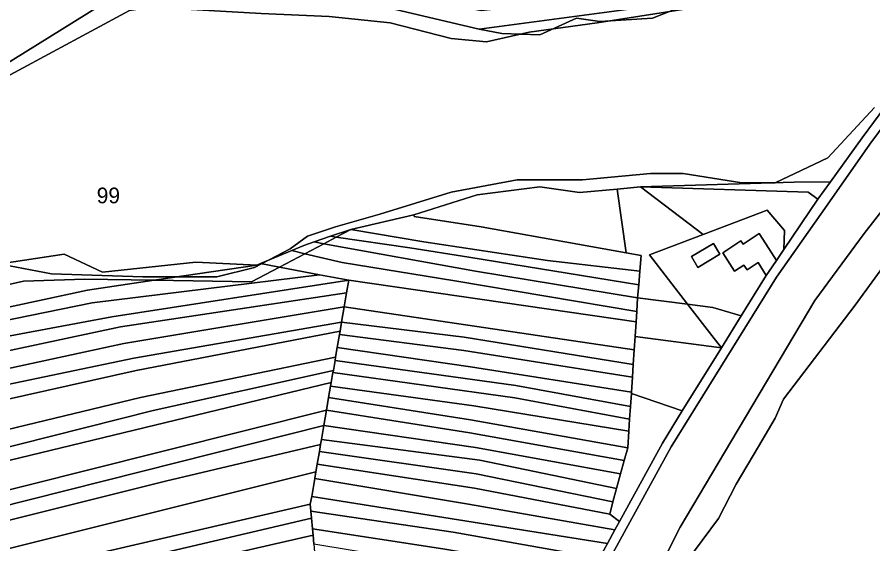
# Model space of a CAD drawing. Extents: x -537068 to -534056, y -1176840 to -1172401.
# Drawn here: x -535241.9 to -534968.9, y -1175937.1 to -1175769.2 of the extents above; entities that cross this region are included whole.
import ezdxf

# ---------------------------------------------------------------- set-up
doc = ezdxf.new("R2010")
doc.units = 0
for name, color, linetype in [('95560013', 7, 'Continuous'), ('95600013', 7, 'Continuous'), ('95630013', 7, 'Continuous'), ('95640013', 7, 'Continuous'), ('95660013', 7, 'Continuous')]:
    doc.layers.add(name, color=color, linetype=linetype)

msp = doc.modelspace()

# ---------------------------------------------------------------- linework, layer by layer
at = {"layer": '95560013'}
for points in [[(-535093.8, -1175835.96), (-535115.19, -1175832.75), (-535115.29, -1175832.21), (-535095.1, -1175825.79), (-535075.08, -1175823.28), (-535062.41, -1175825.11), (-535050.4, -1175823.98), (-535047.57, -1175844.26)], [(-535023.04, -1175838.49), (-535040.14, -1175844.98), (-535028.03, -1175860.61), (-535043.9, -1175858.67), (-535043.57, -1175854.49), (-535043.22, -1175850.16), (-535042.81, -1175845.11), (-535047.57, -1175844.26), (-535050.4, -1175823.98), (-535043.04, -1175823.29)], [(-535002.6, -1175830.73), (-535023.04, -1175838.49), (-535043.04, -1175823.29), (-534989.46, -1175824.91), (-534986.43, -1175827.21), (-534997.31, -1175843.24), (-534997.06, -1175837.16)], [(-535002.6, -1175830.73), (-534997.06, -1175837.16), (-534997.31, -1175843.24), (-534999.65, -1175846.69), (-535002.01, -1175842.95), (-535005.09, -1175838.09), (-535010.29, -1175841.55), (-535011.03, -1175840.44), (-535016.76, -1175844.25), (-535012.96, -1175850.13), (-535010, -1175848.19), (-535009.01, -1175849.71), (-535005.48, -1175847.43), (-535002.86, -1175851.51), (-535006.68, -1175857.67), (-535010.83, -1175864.37), (-535019.94, -1175861.74), (-535028.03, -1175860.61), (-535040.14, -1175844.98), (-535023.04, -1175838.49)], [(-535093.8, -1175835.96), (-535047.57, -1175844.26), (-535042.81, -1175845.11), (-535043.22, -1175850.16), (-535072.62, -1175846.76), (-535112.1, -1175840.82), (-535135.41, -1175836.85), (-535115.29, -1175832.21), (-535115.19, -1175832.75)], [(-535043.57, -1175854.49), (-535097.72, -1175845.7), (-535116.6, -1175842.75), (-535140.05, -1175839.3), (-535135.41, -1175836.85), (-535112.1, -1175840.82), (-535072.62, -1175846.76), (-535043.22, -1175850.16)], [(-535140.05, -1175839.3), (-535116.6, -1175842.75), (-535097.72, -1175845.7), (-535043.57, -1175854.49), (-535043.9, -1175858.67), (-535095.66, -1175850.09), (-535144.02, -1175841.39)], [(-535102.18, -1175853.19), (-535138.14, -1175847.43), (-535150.05, -1175844.57), (-535144.02, -1175841.39), (-535095.66, -1175850.09), (-535043.9, -1175858.67), (-535044.19, -1175863.05)], [(-535026.7, -1175845.5), (-535024.68, -1175848.95), (-535017.7, -1175844.74), (-535019.74, -1175841.36)], [(-535044.4, -1175866.25), (-535136.05, -1175853.05), (-535145.38, -1175851.28), (-535158.18, -1175848.85), (-535150.05, -1175844.57), (-535138.14, -1175847.43), (-535102.18, -1175853.19), (-535044.19, -1175863.05)], [(-535301.85, -1175877.35), (-535297.59, -1175872.96), (-535219.37, -1175856.17), (-535198.16, -1175853.04), (-535167.13, -1175853.57), (-535158.18, -1175848.85), (-535145.38, -1175851.28), (-535217.93, -1175860.21)], [(-535136.05, -1175853.05), (-535136.74, -1175857.04), (-535208.89, -1175867.91), (-535313.65, -1175890.19), (-535307.82, -1175883.5), (-535306.83, -1175882.48), (-535211.67, -1175864.71)], [(-535301.85, -1175877.35), (-535217.93, -1175860.21), (-535145.38, -1175851.28), (-535136.05, -1175853.05), (-535211.67, -1175864.71), (-535306.83, -1175882.48)], [(-535219.37, -1175856.17), (-535297.59, -1175872.96), (-535295.86, -1175871.17), (-535274.11, -1175861.12), (-535239.83, -1175853.35), (-535220.25, -1175852.67), (-535198.16, -1175853.04)], [(-535044.99, -1175875.22), (-535137.5, -1175861.46), (-535136.74, -1175857.04), (-535136.05, -1175853.05), (-535044.4, -1175866.25), (-535044.71, -1175871.01)], [(-535136.74, -1175857.04), (-535137.5, -1175861.46), (-535207.84, -1175873.23), (-535319.39, -1175897.37), (-535317.62, -1175894.74), (-535313.65, -1175890.19), (-535208.89, -1175867.91)], [(-535020.24, -1175870.67), (-535017.19, -1175874.61), (-535044.71, -1175871.01), (-535044.4, -1175866.25), (-535044.19, -1175863.05), (-535043.9, -1175858.67), (-535028.03, -1175860.61)], [(-535137.5, -1175861.46), (-535138.35, -1175866.38), (-535204.63, -1175877.91), (-535254.59, -1175888.3), (-535324.19, -1175904.5), (-535319.39, -1175897.37), (-535207.84, -1175873.23)], [(-535044.99, -1175875.22), (-535045.3, -1175879.92), (-535099.27, -1175871.18), (-535138.35, -1175866.38), (-535137.5, -1175861.46)], [(-535020.24, -1175870.67), (-535028.03, -1175860.61), (-535019.94, -1175861.74), (-535010.83, -1175864.37), (-535017.19, -1175874.61)], [(-535324.19, -1175904.5), (-535254.59, -1175888.3), (-535204.63, -1175877.91), (-535138.35, -1175866.38), (-535138.84, -1175869.24), (-535203.94, -1175881.8), (-535253.84, -1175892.92), (-535330.15, -1175913.36)], [(-535138.84, -1175869.24), (-535138.35, -1175866.38), (-535099.27, -1175871.18), (-535045.3, -1175879.92), (-535045.56, -1175883.91), (-535099.38, -1175875.46), (-535139.02, -1175870.29)], [(-535245.21, -1175900.68), (-535297.9, -1175915.28), (-535335.82, -1175927.11), (-535336.74, -1175923.15), (-535330.15, -1175913.36), (-535253.84, -1175892.92), (-535203.94, -1175881.8), (-535138.84, -1175869.24), (-535139.02, -1175870.29), (-535139.74, -1175874.45), (-535140.26, -1175877.53), (-535202.54, -1175890.38)], [(-535099.38, -1175875.46), (-535045.56, -1175883.91), (-535045.88, -1175888.7), (-535097.19, -1175880.69), (-535139.74, -1175874.45), (-535139.02, -1175870.29)], [(-535045.91, -1175889.14), (-535045.88, -1175888.7), (-535045.56, -1175883.91), (-535045.3, -1175879.92), (-535044.99, -1175875.22), (-535044.71, -1175871.01), (-535017.19, -1175874.61), (-535029.65, -1175894.7)], [(-535140.45, -1175878.61), (-535140.26, -1175877.53), (-535139.74, -1175874.45), (-535097.19, -1175880.69), (-535045.88, -1175888.7), (-535045.91, -1175889.14), (-535046.18, -1175893.26), (-535082.73, -1175886.57)], [(-535297.9, -1175915.28), (-535245.21, -1175900.68), (-535202.54, -1175890.38), (-535140.26, -1175877.53), (-535140.45, -1175878.61), (-535140.99, -1175881.77), (-535198.45, -1175894.61), (-535295.84, -1175919.08), (-535335.09, -1175930.24), (-535335.82, -1175927.11)], [(-535140.45, -1175878.61), (-535082.73, -1175886.57), (-535046.18, -1175893.26), (-535046.45, -1175897.3), (-535083.13, -1175890.54), (-535141.12, -1175882.5), (-535140.99, -1175881.77)], [(-535141.12, -1175882.5), (-535141.67, -1175885.68), (-535297.4, -1175923.22), (-535334.35, -1175933.46), (-535335.09, -1175930.24), (-535295.84, -1175919.08), (-535198.45, -1175894.61), (-535140.99, -1175881.77)], [(-535046.45, -1175897.3), (-535046.7, -1175901.19), (-535096.14, -1175893.12), (-535141.86, -1175886.78), (-535141.67, -1175885.68), (-535141.12, -1175882.5), (-535083.13, -1175890.54)], [(-535334.35, -1175933.46), (-535297.4, -1175923.22), (-535141.67, -1175885.68), (-535141.86, -1175886.78), (-535142.48, -1175890.39), (-535143.19, -1175894.5), (-535220.72, -1175913.88), (-535332.39, -1175941.92)], [(-535096.14, -1175893.12), (-535046.7, -1175901.19), (-535047.05, -1175906.47), (-535097.2, -1175897.49), (-535142.48, -1175890.39), (-535141.86, -1175886.78)], [(-535048.17, -1175910.48), (-535097.45, -1175901.68), (-535143.19, -1175894.5), (-535142.48, -1175890.39), (-535097.2, -1175897.49), (-535047.05, -1175906.47)], [(-535047.05, -1175906.47), (-535046.7, -1175901.19), (-535046.45, -1175897.3), (-535046.18, -1175893.26), (-535045.91, -1175889.14), (-535029.65, -1175894.7), (-535036.02, -1175904.98), (-535049.68, -1175929.91), (-535052.8, -1175927.58), (-535051.86, -1175923.72), (-535050.67, -1175919.47), (-535049.37, -1175914.79), (-535048.17, -1175910.48)], [(-535144.02, -1175899.33), (-535331.33, -1175946.51), (-535332.39, -1175941.92), (-535220.72, -1175913.88), (-535143.19, -1175894.5)], [(-535095.62, -1175906.33), (-535144.02, -1175899.33), (-535143.19, -1175894.5), (-535097.45, -1175901.68), (-535048.17, -1175910.48), (-535049.37, -1175914.79)], [(-535145.06, -1175905.39), (-535194.58, -1175917.13), (-535330.29, -1175951), (-535331.33, -1175946.51), (-535144.02, -1175899.33), (-535144.8, -1175903.85)], [(-535144.02, -1175899.33), (-535095.62, -1175906.33), (-535049.37, -1175914.79), (-535050.67, -1175919.47), (-535094.22, -1175910.43), (-535144.8, -1175903.85)], [(-535144.8, -1175903.85), (-535094.22, -1175910.43), (-535050.67, -1175919.47), (-535051.86, -1175923.72), (-535095.41, -1175914.8), (-535145.44, -1175907.61), (-535145.06, -1175905.39)], [(-535194.58, -1175917.13), (-535145.06, -1175905.39), (-535145.44, -1175907.61), (-535146.13, -1175911.66), (-535146.55, -1175914.1), (-535328.33, -1175959.48), (-535330.29, -1175951)], [(-535051.86, -1175923.72), (-535052.8, -1175927.58), (-535095.95, -1175919.32), (-535146.13, -1175911.66), (-535145.44, -1175907.61), (-535095.41, -1175914.8)], [(-535052.8, -1175927.58), (-535049.68, -1175929.91), (-535051.15, -1175932.6), (-535097.85, -1175924.46), (-535146.92, -1175916.27), (-535146.55, -1175914.1), (-535146.13, -1175911.66), (-535095.95, -1175919.32)], [(-535148.33, -1175924.47), (-535326.87, -1175965.76), (-535328.33, -1175959.48), (-535146.55, -1175914.1), (-535146.92, -1175916.27), (-535147.9, -1175921.98)], [(-535051.15, -1175932.6), (-535053.54, -1175936.95), (-535101.05, -1175929.43), (-535147.9, -1175921.98), (-535146.92, -1175916.27), (-535097.85, -1175924.46)], [(-535055.84, -1175941.16), (-535062, -1175940.6), (-535102.78, -1175933.38), (-535148.13, -1175926.69), (-535148.33, -1175924.47), (-535147.9, -1175921.98), (-535101.05, -1175929.43), (-535053.54, -1175936.95)], [(-535148.13, -1175926.69), (-535147.93, -1175928.92), (-535290.32, -1175962.24), (-535326.01, -1175969.46), (-535326.87, -1175965.76), (-535148.33, -1175924.47)], [(-535102.78, -1175933.38), (-535062, -1175940.6), (-535062.78, -1175945.98), (-535106.07, -1175938.71), (-535147.63, -1175932.3), (-535147.93, -1175928.92), (-535148.13, -1175926.69)], [(-535147.93, -1175928.92), (-535147.63, -1175932.3), (-535147.45, -1175934.33), (-535288.27, -1175966.48), (-535325.11, -1175973.34), (-535326.01, -1175969.46), (-535290.32, -1175962.24)], [(-535063.51, -1175950.98), (-535147.2, -1175937.21), (-535147.45, -1175934.33), (-535147.63, -1175932.3), (-535106.07, -1175938.71), (-535062.78, -1175945.98)], [(-535146.32, -1175947.1), (-535282.18, -1175976.18), (-535321.72, -1175983.04), (-535323.82, -1175978.94), (-535325.11, -1175973.34), (-535288.27, -1175966.48), (-535147.45, -1175934.33), (-535147.2, -1175937.21), (-535146.77, -1175942.01)]]:
    msp.add_lwpolyline(points, close=True, dxfattribs=at)
at = {"layer": '95600013'}
msp.add_lwpolyline([(-535336.79, -1175832.88), (-535317.96, -1175809.63), (-535313.29, -1175805.13), (-535301.28, -1175793.55), (-535286.39, -1175776.99), (-535271.4, -1175765.94), (-535247.87, -1175747.4), (-535227.44, -1175729.49), (-535216.91, -1175723.46), (-535201.51, -1175713.09), (-535168.68, -1175739.06), (-535159.9, -1175742.34), (-535152.61, -1175745.06), (-535149.83, -1175762.25), (-535207.84, -1175760.65), (-535247.13, -1175785.26), (-535307.86, -1175812.82), (-535328.63, -1175827.45), (-535350.95, -1175850.74)], close=True, dxfattribs=at)
at = {"layer": '95630013'}
for points in [[(-535247.13, -1175785.26), (-535207.84, -1175760.65), (-535191.06, -1175762.77), (-535169.69, -1175762.63), (-535149.83, -1175762.25), (-535125.27, -1175766.1), (-535121.13, -1175766.75), (-535094.47, -1175772.94), (-535087.2, -1175774.4), (-535075.1, -1175774.78), (-535063.37, -1175769.44), (-535055.93, -1175770.6), (-535039.2, -1175769.49), (-535024.33, -1175763.57), (-535019.28, -1175766.12), (-535002.34, -1175764.96), (-534963.81, -1175759.59)], [(-535048.44, -1175967.44), (-535030.38, -1175931.76), (-535016.19, -1175907.93), (-534987.38, -1175859.54), (-534971.62, -1175838.1), (-534919.46, -1175771.3)], [(-534919.46, -1175771.3), (-534971.62, -1175838.1), (-534987.38, -1175859.54), (-535016.19, -1175907.93), (-535030.38, -1175931.76), (-535048.44, -1175967.44)], [(-534950.61, -1175778.33), (-534972.28, -1175807.68), (-534982.43, -1175821.7), (-534993.98, -1175821.82), (-535043.04, -1175823.29), (-535050.4, -1175823.98), (-535062.41, -1175825.11), (-535075.08, -1175823.28), (-535095.1, -1175825.79), (-535115.29, -1175832.21), (-535135.41, -1175836.85), (-535141.85, -1175839.03), (-535147.14, -1175840.83), (-535150.37, -1175841.93), (-535154.26, -1175843.56), (-535164.2, -1175847.71), (-535165.43, -1175848.22), (-535184.89, -1175847.28), (-535214.67, -1175850.44), (-535226.82, -1175844.7), (-535248.82, -1175848.04)], [(-535063.2, -1175960.77), (-535033.24, -1175906.1), (-534999.62, -1175852.1), (-534983.44, -1175829.08), (-534969.88, -1175809.65), (-534947.07, -1175779.02)]]:
    msp.add_lwpolyline(points, dxfattribs=at)
for points in [[(-535055.93, -1175770.6), (-535063.37, -1175769.44), (-535075.1, -1175774.78), (-535087.2, -1175774.4), (-535094.47, -1175772.94), (-535024.33, -1175763.57), (-535039.2, -1175769.49)], [(-534993.98, -1175821.82), (-534982.43, -1175821.7), (-534986.43, -1175827.21), (-534989.46, -1175824.91), (-535043.04, -1175823.29)], [(-535141.85, -1175839.03), (-535135.41, -1175836.85), (-535140.05, -1175839.3)], [(-535140.05, -1175839.3), (-535144.02, -1175841.39), (-535147.14, -1175840.83), (-535141.85, -1175839.03)], [(-535144.02, -1175841.39), (-535150.05, -1175844.57), (-535154.26, -1175843.56), (-535150.37, -1175841.93), (-535147.14, -1175840.83)], [(-535266.46, -1175853.08), (-535248.82, -1175848.04), (-535226.82, -1175844.7), (-535214.67, -1175850.44), (-535184.89, -1175847.28), (-535165.43, -1175848.22), (-535198.16, -1175853.04), (-535220.25, -1175852.67), (-535239.83, -1175853.35), (-535274.11, -1175861.12), (-535295.86, -1175871.17), (-535280.94, -1175860.21)], [(-535150.05, -1175844.57), (-535158.18, -1175848.85), (-535164.2, -1175847.71), (-535154.26, -1175843.56)], [(-535164.2, -1175847.71), (-535158.18, -1175848.85), (-535167.13, -1175853.57), (-535198.16, -1175853.04), (-535165.43, -1175848.22)]]:
    msp.add_lwpolyline(points, close=True, dxfattribs=at)
at = {"layer": '95640013'}
for points in [[(-535025.18, -1175758.03), (-535004.49, -1175753.79), (-534961.92, -1175746.47), (-534964.16, -1175752.21), (-535024.33, -1175763.57), (-535094.47, -1175772.94), (-535121.13, -1175766.75), (-535141.07, -1175741.96), (-535121.28, -1175756.78), (-535112.39, -1175763.44), (-535093.81, -1175767.01), (-535079.13, -1175765.46), (-535050.13, -1175761.47)], [(-535010, -1175848.19), (-535012.96, -1175850.13), (-535016.76, -1175844.25), (-535011.03, -1175840.44), (-535010.29, -1175841.55), (-535005.09, -1175838.09), (-535002.01, -1175842.95), (-534999.65, -1175846.69), (-535002.19, -1175850.43), (-535002.86, -1175851.51), (-535005.48, -1175847.43), (-535009.01, -1175849.71)], [(-535019.74, -1175841.36), (-535017.7, -1175844.74), (-535024.68, -1175848.95), (-535026.7, -1175845.5)]]:
    msp.add_lwpolyline(points, close=True, dxfattribs=at)
for points in [[(-534947.07, -1175779.02), (-534969.88, -1175809.65), (-534983.44, -1175829.08), (-534999.62, -1175852.1), (-535033.24, -1175906.1), (-535063.2, -1175960.77)], [(-535055.84, -1175941.16), (-535053.54, -1175936.95), (-535051.15, -1175932.6), (-535049.68, -1175929.91), (-535036.02, -1175904.98), (-535029.65, -1175894.7), (-535017.19, -1175874.61), (-535010.83, -1175864.37), (-535006.68, -1175857.67), (-535002.86, -1175851.51), (-535002.19, -1175850.43), (-534999.65, -1175846.69), (-534997.31, -1175843.24), (-534986.43, -1175827.21), (-534982.43, -1175821.7), (-534972.28, -1175807.68), (-534950.61, -1175778.33)]]:
    msp.add_lwpolyline(points, dxfattribs=at)
at = {"layer": '95660013'}
for points in [[(-534965.81, -1175747), (-534993.12, -1175755), (-535000, -1175757), (-535005.87, -1175762), (-535024.81, -1175766), (-535056.81, -1175771), (-535078.5, -1175774), (-535092.12, -1175777), (-535103.37, -1175776), (-535122.81, -1175771), (-535142.37, -1175769), (-535164, -1175768), (-535199.37, -1175766), (-535206, -1175767), (-535267.31, -1175800)], [(-535267.31, -1175800), (-535206, -1175767), (-535199.37, -1175766), (-535164, -1175768), (-535142.37, -1175769), (-535122.81, -1175771), (-535103.37, -1175776), (-535092.12, -1175777), (-535078.5, -1175774), (-535056.81, -1175771), (-535024.81, -1175766), (-535005.87, -1175762), (-535000, -1175757), (-534993.12, -1175755), (-534965.81, -1175747)], [(-535246.5, -1175848), (-535230.87, -1175851), (-535201.81, -1175852), (-535178.19, -1175852), (-535166.12, -1175849), (-535154.81, -1175843), (-535149.19, -1175839), (-535140.31, -1175836), (-535126.12, -1175832), (-535103.37, -1175825), (-535082.31, -1175821), (-535061.5, -1175821), (-535039.81, -1175819), (-535029.37, -1175819), (-535010.62, -1175822), (-535000, -1175822), (-534983.19, -1175814), (-534968.31, -1175798)], [(-534968.31, -1175798), (-534983.19, -1175814), (-535000, -1175822), (-535010.62, -1175822), (-535029.37, -1175819), (-535039.81, -1175819), (-535061.5, -1175821), (-535082.31, -1175821), (-535103.37, -1175825), (-535126.12, -1175832), (-535140.31, -1175836), (-535149.19, -1175839), (-535154.81, -1175843), (-535166.12, -1175849), (-535178.19, -1175852), (-535201.81, -1175852), (-535230.87, -1175851), (-535246.5, -1175848)], [(-534954.87, -1175834), (-534974.5, -1175861), (-534997.37, -1175891), (-535000, -1175897), (-535005.37, -1175906), (-535012.5, -1175918), (-535018.12, -1175929), (-535028.5, -1175943)], [(-535028.5, -1175943), (-535018.12, -1175929), (-535012.5, -1175918), (-535005.37, -1175906), (-535000, -1175897), (-534997.37, -1175891), (-534974.5, -1175861), (-534954.87, -1175834)]]:
    msp.add_lwpolyline(points, dxfattribs=at)

# ---------------------------------------------------------------- texts
msp.add_text('99', height=5, rotation=0, dxfattribs=at).set_placement((-535216.48, -1175828.5))

doc.saveas('drawing.dxf')
